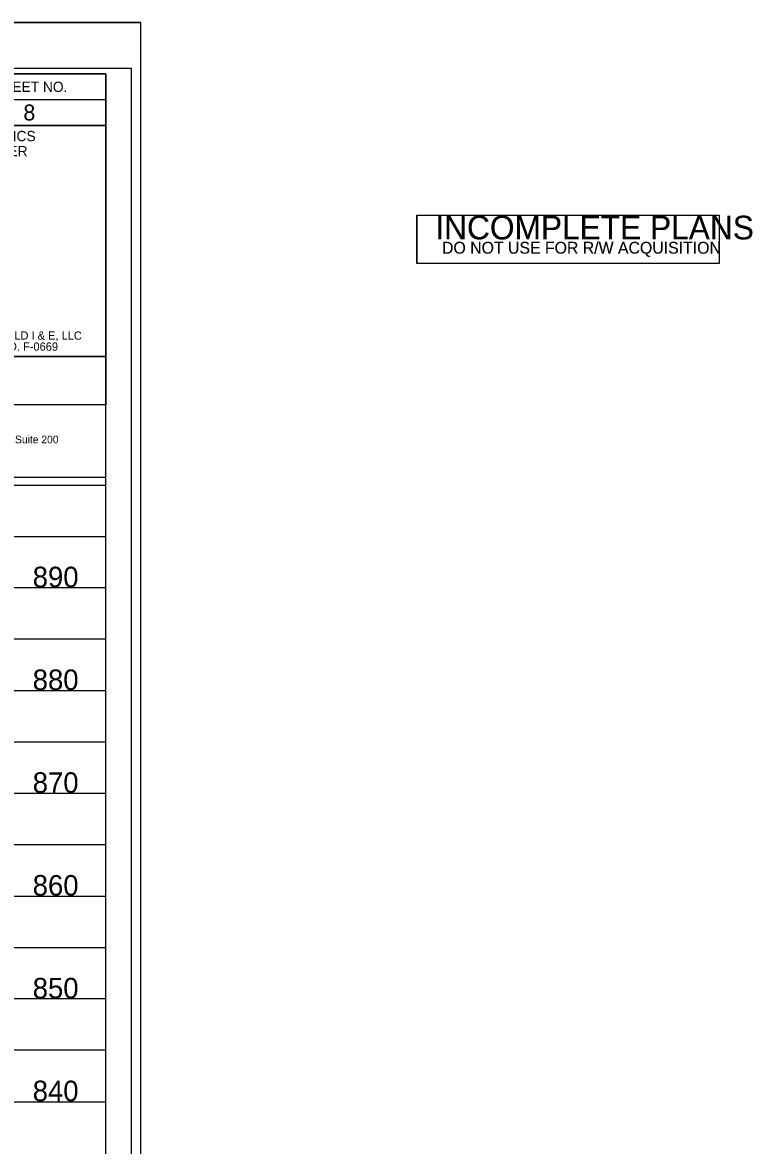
# Model space of a CAD drawing. Extents: x 1967929 to 1975641, y 546296 to 568534.
# Drawn here: x 1971491 to 1971846, y 567988 to 568534 of the extents above; entities that cross this region are included whole.
import ezdxf

# ---------------------------------------------------------------- set-up
doc = ezdxf.new("R2010")
doc.units = 0
for name, color, linetype in [('Exist Vertical Profile Vertical Axis Label', 7, 'Continuous'), ('Old_Level_2', 7, 'Continuous'), ('Old_Level_42', 7, 'Continuous'), ('Old_Level_45', 7, 'Continuous'), ('Scratch_Level_1', 7, 'Continuous'), ('Sheet Cutting Line CELL', 7, 'Continuous'), ('Sheet Plot Border Inside CELL', 7, 'Continuous'), ('Sheet Plot Border Outside CELL', 7, 'Continuous'), ('Sheet Profile CELL', 7, 'Continuous'), ('Sheet Profile Grid Major CELL', 7, 'Continuous'), ('Sheet Profile Grid Middle CELL', 7, 'Continuous'), ('Sheet Sticker Incomplete CELL', 7, 'Continuous')]:
    doc.layers.add(name, color=color, linetype=linetype)

msp = doc.modelspace()

# ---------------------------------------------------------------- linework, layer by layer
at = {"layer": 'Old_Level_42'}
msp.add_lwpolyline([(1971531.45, 568312.51), (1971331.4, 568312.51), (1971331.4, 568347.81)], dxfattribs=at)
at = {"layer": 'Scratch_Level_1'}
for p, q in [((1971331.4, 568371.31), (1971531.44, 568371.31)), ((1971531.44, 568371.3), (1971531.44, 568347.8)), ((1971531.44, 568347.81), (1971331.4, 568347.81))]:
    msp.add_line(p, q, dxfattribs=at)
at = {"layer": 'Sheet Cutting Line CELL'}
msp.add_line((1969864.45, 568533.86), (1971548.45, 568533.86), dxfattribs=at)
at = {"layer": 'Sheet Plot Border Inside CELL'}
msp.add_lwpolyline([(1969877.45, 567456.31), (1971543.95, 567456.31), (1971543.95, 568511.41), (1969877.45, 568511.41)], close=True, dxfattribs=at)
at = {"layer": 'Sheet Plot Border Outside CELL'}
msp.add_lwpolyline([(1969864.45, 567433.86), (1971548.45, 567433.86), (1971548.45, 568533.86), (1969864.45, 568533.86)], close=True, dxfattribs=at)
at = {"layer": 'Sheet Profile CELL'}
for p, q in [((1971331.4, 568496.31), (1971531.45, 568496.31)), ((1970031.45, 568008.86), (1971531.45, 568008.86))]:
    msp.add_line(p, q, dxfattribs=at)
for points in [[(1971531.45, 568508.86), (1970031.45, 568508.86), (1970031.45, 567458.86), (1971531.45, 567458.86)], [(1971331.4, 568508.86), (1971531.45, 568508.86), (1971531.45, 568483.81), (1971331.4, 568483.81)], [(1971431.45, 568483.81), (1971531.45, 568483.81), (1971531.45, 568371.31), (1971431.45, 568371.31)]]:
    msp.add_lwpolyline(points, close=True, dxfattribs=at)
msp.add_lwpolyline([(1971531.45, 568312.51), (1971331.4, 568312.51), (1971331.4, 568347.81)], dxfattribs=at)
at = {"layer": 'Sheet Profile Grid Major CELL'}
for points in [[(1971481.45, 568312.51), (1971481.45, 568008.86), (1971531.45, 568008.86)], [(1971531.45, 568258.86), (1970031.45, 568258.86), (1970031.45, 568308.86), (1971331.4, 568308.86)], [(1971531.45, 568258.86), (1970031.45, 568258.86), (1970031.45, 568308.86), (1971531.45, 568308.86)], [(1971481.45, 568277.21), (1971481.45, 568008.86), (1971531.45, 568008.86)], [(1971531.45, 568158.86), (1970031.45, 568158.86), (1970031.45, 568208.86), (1971531.45, 568208.86)], [(1971531.45, 568058.86), (1970031.45, 568058.86), (1970031.45, 568108.86), (1971531.45, 568108.86)]]:
    msp.add_lwpolyline(points, dxfattribs=at)
at = {"layer": 'Sheet Profile Grid Middle CELL'}
for points in [[(1971331.45, 568333.86), (1970031.45, 568333.86), (1970031.45, 568283.86), (1971531.45, 568283.86)], [(1971531.45, 568233.86), (1970031.45, 568233.86), (1970031.45, 568183.86), (1971531.45, 568183.86)], [(1971531.45, 568133.86), (1970031.45, 568133.86), (1970031.45, 568083.86), (1971531.45, 568083.86)], [(1971531.45, 568033.86), (1970031.45, 568033.86)]]:
    msp.add_lwpolyline(points, dxfattribs=at)
at = {"layer": 'Sheet Sticker Incomplete CELL'}
for points in [[(1971682.78, 568416.64), (1971682.78, 568440.14), (1971829.78, 568440.14), (1971829.78, 568416.64)], [(1971682.86, 568416.64), (1971682.86, 568440.14), (1971829.86, 568440.14), (1971829.86, 568416.64)]]:
    msp.add_lwpolyline(points, close=True, dxfattribs=at)

# ---------------------------------------------------------------- texts
at = {"layer": 'Exist Vertical Profile Vertical Axis Label'}
for s, p in [('890', (1971495.92, 568259.11)), ('880', (1971495.92, 568209.11)), ('870', (1971495.92, 568159.11)), ('860', (1971495.92, 568109.11)), ('850', (1971495.92, 568059.11)), ('840', (1971495.92, 568009.11))]:
    msp.add_text(s, height=10, dxfattribs=at).set_placement(p)
at = {"layer": 'Old_Level_2'}
msp.add_text('930 Main Campus Drive, Suite 200', height=3.75, rotation=360, dxfattribs=at).set_placement((1971430.73, 568329.13))
at = {"layer": 'Old_Level_45'}
for s, p in [('MOTT MACDONALD I & E, LLC', (1971442.81, 568379.54)), (' LICENSE NO. F-0669', (1971454.2, 568374.19))]:
    msp.add_text(s, height=4.0179, dxfattribs=at).set_placement(p)
at = {"layer": 'Sheet Profile CELL'}
for s, height, p in [('SHEET NO.', 5, (1971476.75, 568500.06)), ('8', 7.75, (1971491.4, 568486.19)), ('HYDRAULICS', 5, (1971454.25, 568476.11)), ('ENGINEER', 5, (1971458.5, 568468.76))]:
    msp.add_text(s, height=height, dxfattribs=at).set_placement(p)
at = {"layer": 'Sheet Sticker Incomplete CELL'}
for s, height, p in [('INCOMPLETE PLANS', 11.52, (1971691.73, 568428.34)), ('INCOMPLETE PLANS', 11.52, (1971691.81, 568428.34)), ('DO NOT USE FOR R/W ACQUISITION', 5.76, (1971694.98, 568421.39)), ('DO NOT USE FOR R/W ACQUISITION', 5.76, (1971695.06, 568421.39))]:
    msp.add_text(s, height=height, dxfattribs=at).set_placement(p)

doc.saveas('drawing.dxf')
